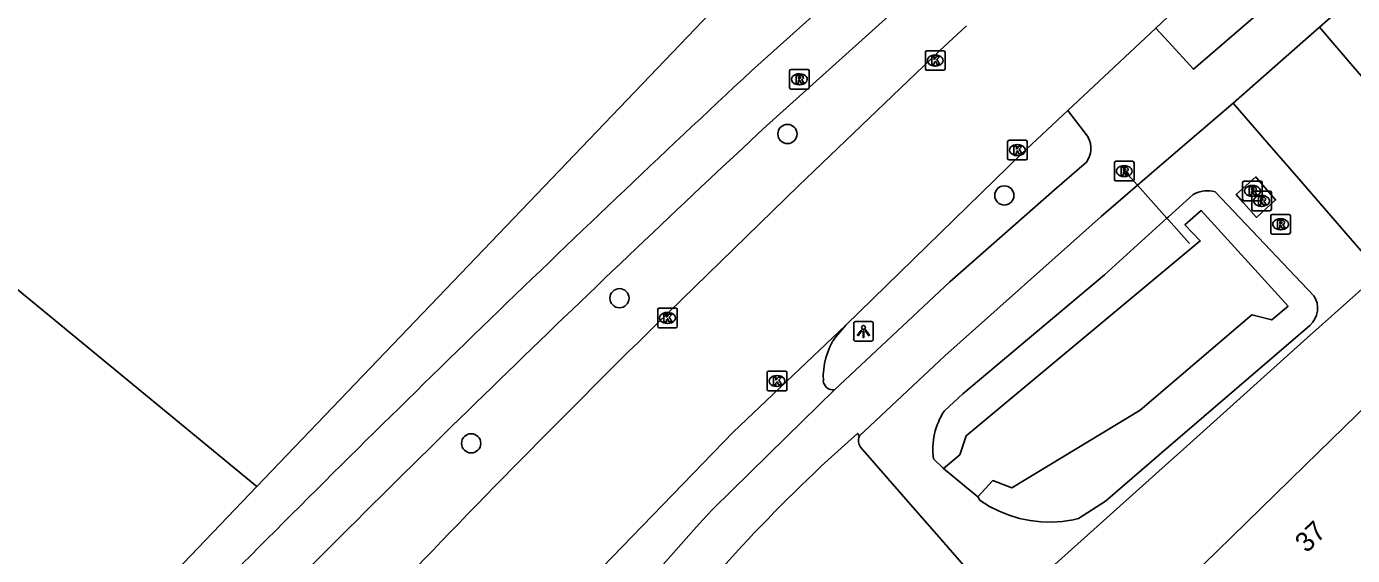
# Model space of a CAD drawing. Extents: x 156141 to 158132, y 385651 to 388399.
# Drawn here: x 156441.8 to 156509.4, y 386826.5 to 386853.4 of the extents above; entities that cross this region are included whole.
import ezdxf

# ---------------------------------------------------------------- set-up
doc = ezdxf.new("R2010")
doc.units = 0
for name, color, linetype in [('IMGEO_Boom', 7, 'Continuous'), ('IMGEO_Damwand', 7, 'Continuous'), ('IMGEO_Duiker', 7, 'Continuous'), ('IMGEO_Fietspad_gesloten', 7, 'Continuous'), ('IMGEO_Groenvoorziening', 7, 'Continuous'), ('IMGEO_Kolk', 7, 'Continuous'), ('IMGEO_Lichtpunt', 7, 'Continuous'), ('IMGEO_Loofbos', 7, 'Continuous'), ('IMGEO_Muur', 7, 'Continuous'), ('IMGEO_Pand', 7, 'Continuous'), ('IMGEO_Pand_nummerreeks', 7, 'Continuous'), ('IMGEO_Rijbaan_lokaal_gesloten', 7, 'Continuous'), ('IMGEO_Rijbaan_lokaal_open', 7, 'Continuous'), ('IMGEO_Rioolput', 7, 'Continuous'), ('IMGEO_Waterloop', 7, 'Continuous')]:
    doc.layers.add(name, color=color, linetype=linetype)

msp = doc.modelspace()

# ---------------------------------------------------------------- linework, layer by layer
at = {"layer": 'IMGEO_Boom'}
for centre in [(156480.568, 386847.96), (156491.626, 386844.826), (156472.004, 386839.585), (156464.441, 386832.183)]:
    msp.add_circle(centre, 0.489, dxfattribs=at)
at = {"layer": 'IMGEO_Damwand'}
msp.add_lwpolyline([(156506.093, 386839.179), (156501.667, 386844.053), (156500.837, 386843.324)], dxfattribs=at)
at = {"layer": 'IMGEO_Duiker'}
msp.add_lwpolyline([(156501.074, 386842.375), (156500, 386843.576), (156499.919, 386843.667), (156498.417, 386845.347), (156497.76, 386846.082)], dxfattribs=at)
at = {"layer": 'IMGEO_Fietspad_gesloten'}
for points in [[(156507.703, 386853.398), (156512.09, 386857.271), (156538.111, 386880.059)], [(156486.891, 386858.499), (156478.74, 386851.184)], [(156479.499, 386848.37), (156488.601, 386856.57)], [(156503.3, 386849.53), (156507.703, 386853.398)], [(156484.24, 386832.56), (156488.601, 386836.651), (156496.558, 386843.756), (156498.417, 386845.347), (156500, 386846.703), (156503.3, 386849.53)], [(156494.861, 386849.158), (156495.912, 386847.781)], [(156495.815, 386846.527), (156494.181, 386845.112), (156488.853, 386840.427), (156482.97, 386834.92)]]:
    msp.add_lwpolyline(points, dxfattribs=at)
for centre, radius, start, end in [((157123.713, 386159.175), 945.974, 132.985141, 135.281185), ((157069.291, 386214.847), 865.567, 132.95264, 135.361886), ((156494.838, 386847.233), 1.205, 324.12857, 27.02511)]:
    msp.add_arc(centre, radius, start, end, dxfattribs=at)
at = {"layer": 'IMGEO_Groenvoorziening'}
for points in [[(156541.121, 386876.586), (156521.047, 386859.086), (156514.467, 386853.349), (156510.617, 386850.009), (156509.404, 386851.42), (156507.703, 386853.398)], [(156503.3, 386849.53), (156505.031, 386847.528), (156506.198, 386846.177), (156510.785, 386840.87), (156507.066, 386837.556), (156500.596, 386831.732), (156500, 386831.198), (156491.571, 386823.646)], [(156503.825, 386844.452), (156503.449, 386844.872), (156504.446, 386845.766), (156504.581, 386845.61), (156505.46, 386844.595), (156504.495, 386843.703), (156503.825, 386844.452)], [(156501.249, 386844.873), (156500, 386843.741), (156499.919, 386843.667), (156496.734, 386840.782), (156489.517, 386834.707), (156488.569, 386833.834)], [(156507.413, 386839.712), (156502.375, 386845.014), (156502.239, 386845.043)], [(156490.282, 386829.462), (156490.398, 386829.263), (156490.866, 386828.97), (156491.358, 386828.719), (156491.87, 386828.514), (156492.398, 386828.355), (156492.939, 386828.244), (156493.487, 386828.181), (156494.039, 386828.168), (156494.59, 386828.205), (156495.135, 386828.29), (156495.411, 386828.352), (156496.782, 386829.23), (156500, 386831.998), (156507.213, 386838.2)], [(156488.019, 386831.388), (156488.526, 386830.905)]]:
    msp.add_lwpolyline(points, dxfattribs=at)
for centre, radius, start, end in [((156501.987, 386843.543), 1.521, 80.45967, 119.02761), ((156506.418, 386839.074), 1.182, 312.27222, 32.65765), ((156491.507, 386831.888), 3.524, 146.4902, 188.16464)]:
    msp.add_arc(centre, radius, start, end, dxfattribs=at)
at = {"layer": 'IMGEO_Kolk'}
for p, q in [((156487.602, 386851.28), (156487.602, 386852.132)), ((156487.677, 386852.206), (156488.529, 386852.206)), ((156488.09, 386851.986), (156488.115, 386851.986)), ((156488.603, 386852.132), (156488.603, 386851.28)), ((156488.529, 386851.206), (156487.677, 386851.206)), ((156488.113, 386851.426), (156488.088, 386851.426)), ((156491.797, 386846.712), (156491.797, 386847.564)), ((156491.872, 386847.638), (156492.724, 386847.638)), ((156492.285, 386847.418), (156492.31, 386847.418)), ((156492.798, 386847.564), (156492.798, 386846.712)), ((156492.724, 386846.638), (156491.872, 386846.638)), ((156492.308, 386846.858), (156492.283, 386846.858)), ((156474.026, 386839.077), (156474.878, 386839.077)), ((156473.951, 386838.151), (156473.951, 386839.003)), ((156474.439, 386838.857), (156474.464, 386838.857)), ((156474.952, 386839.003), (156474.952, 386838.151)), ((156474.878, 386838.077), (156474.026, 386838.077)), ((156474.462, 386838.297), (156474.437, 386838.297)), ((156479.534, 386834.937), (156479.534, 386835.789)), ((156479.609, 386835.863), (156480.461, 386835.863)), ((156480.022, 386835.643), (156480.047, 386835.643)), ((156480.535, 386835.789), (156480.535, 386834.937)), ((156480.045, 386835.083), (156480.02, 386835.083)), ((156480.461, 386834.863), (156479.609, 386834.863))]:
    msp.add_line(p, q, dxfattribs=at)
for points in [[(156487.602, 386851.28), (156487.602, 386852.132)], [(156487.677, 386852.206), (156488.529, 386852.206)], [(156487.923, 386851.906), (156488.046, 386851.906), (156488.046, 386851.755), (156488.176, 386851.906), (156488.34, 386851.906), (156488.194, 386851.755), (156488.347, 386851.506), (156488.195, 386851.506), (156488.11, 386851.67), (156488.046, 386851.603), (156488.046, 386851.506), (156487.923, 386851.506), (156487.923, 386851.906)], [(156488.603, 386852.132), (156488.603, 386851.28)], [(156488.529, 386851.206), (156487.677, 386851.206)], [(156491.797, 386846.712), (156491.797, 386847.564)], [(156491.872, 386847.638), (156492.724, 386847.638)], [(156492.118, 386847.338), (156492.241, 386847.338), (156492.241, 386847.187), (156492.371, 386847.338), (156492.535, 386847.338), (156492.389, 386847.187), (156492.542, 386846.938), (156492.39, 386846.938), (156492.305, 386847.102), (156492.241, 386847.035), (156492.241, 386846.938), (156492.118, 386846.938), (156492.118, 386847.338)], [(156492.798, 386847.564), (156492.798, 386846.712)], [(156492.724, 386846.638), (156491.872, 386846.638)], [(156474.026, 386839.077), (156474.878, 386839.077)], [(156473.951, 386838.151), (156473.951, 386839.003)], [(156474.272, 386838.777), (156474.395, 386838.777), (156474.395, 386838.626), (156474.525, 386838.777), (156474.689, 386838.777), (156474.543, 386838.626), (156474.696, 386838.377), (156474.544, 386838.377), (156474.459, 386838.541), (156474.395, 386838.474), (156474.395, 386838.377), (156474.272, 386838.377), (156474.272, 386838.777)], [(156474.952, 386839.003), (156474.952, 386838.151)], [(156474.878, 386838.077), (156474.026, 386838.077)], [(156479.534, 386834.937), (156479.534, 386835.789)], [(156479.609, 386835.863), (156480.461, 386835.863)], [(156480.535, 386835.789), (156480.535, 386834.937)], [(156479.855, 386835.563), (156479.978, 386835.563), (156479.978, 386835.412), (156480.108, 386835.563), (156480.272, 386835.563), (156480.126, 386835.412), (156480.279, 386835.163), (156480.127, 386835.163), (156480.042, 386835.327), (156479.978, 386835.26), (156479.978, 386835.163), (156479.855, 386835.163), (156479.855, 386835.563)], [(156480.461, 386834.863), (156479.609, 386834.863)]]:
    msp.add_lwpolyline(points, dxfattribs=at)
for centre, start, end in [((156487.679, 386852.13), 91.55205, 178.44795), ((156487.679, 386852.13), 91.55205, 178.44795), ((156488.527, 386852.13), 1.55205, 88.44795), ((156488.527, 386852.13), 1.55205, 88.44795), ((156487.679, 386851.282), 181.55205, 268.44795), ((156487.679, 386851.282), 181.55205, 268.44795), ((156488.527, 386851.282), 271.55205, 358.44795), ((156488.527, 386851.282), 271.55205, 358.44795), ((156491.874, 386847.562), 91.55205, 178.44795), ((156491.874, 386847.562), 91.55205, 178.44795), ((156492.722, 386847.562), 1.55205, 88.44795), ((156492.722, 386847.562), 1.55205, 88.44795), ((156491.874, 386846.714), 181.55205, 268.44795), ((156491.874, 386846.714), 181.55205, 268.44795), ((156492.722, 386846.714), 271.55205, 358.44795), ((156492.722, 386846.714), 271.55205, 358.44795), ((156474.028, 386839.001), 91.55205, 178.44795), ((156474.028, 386839.001), 91.55205, 178.44795), ((156474.876, 386839.001), 1.55205, 88.44795), ((156474.876, 386839.001), 1.55205, 88.44795), ((156474.028, 386838.153), 181.55205, 268.44795), ((156474.028, 386838.153), 181.55205, 268.44795), ((156474.876, 386838.153), 271.55205, 358.44795), ((156474.876, 386838.153), 271.55205, 358.44795), ((156479.611, 386835.787), 91.55205, 178.44795), ((156479.611, 386835.787), 91.55205, 178.44795), ((156480.459, 386835.787), 1.55205, 88.44795), ((156480.459, 386835.787), 1.55205, 88.44795), ((156479.611, 386834.939), 181.55205, 268.44795), ((156479.611, 386834.939), 181.55205, 268.44795), ((156480.459, 386834.939), 271.55205, 358.44795), ((156480.459, 386834.939), 271.55205, 358.44795)]:
    msp.add_arc(centre, 0.0765, start, end, dxfattribs=at)
for centre, major_axis, ratio, start_param, end_param in [((156488.089, 386851.706), (-0.387, 0.002), 0.722429, 4.712389, 7.853982), ((156488.114, 386851.706), (-0.39, 0.002), 0.717154, 1.570796, 4.712389), ((156492.284, 386847.138), (-0.387, 0.002), 0.722429, 4.712389, 7.853982), ((156492.309, 386847.138), (-0.39, 0.002), 0.717154, 1.570796, 4.712389), ((156474.438, 386838.577), (-0.387, 0.002), 0.722429, 4.712389, 7.853982), ((156474.463, 386838.577), (-0.39, 0.002), 0.717154, 1.570796, 4.712389), ((156480.021, 386835.363), (-0.387, 0.002), 0.722429, 4.712389, 7.853982), ((156480.046, 386835.363), (-0.39, 0.002), 0.717154, 1.570796, 4.712389)]:
    msp.add_ellipse(centre, major_axis=major_axis, ratio=ratio, start_param=start_param, end_param=end_param, dxfattribs=at)
at = {"layer": 'IMGEO_Lichtpunt'}
for p, q in [((156484.848, 386838.39), (156484.04, 386838.39)), ((156484.848, 386838.39), (156484.04, 386838.39)), ((156483.946, 386838.295), (156483.946, 386837.488)), ((156483.946, 386838.295), (156483.946, 386837.488)), ((156484.942, 386837.488), (156484.942, 386838.295)), ((156484.942, 386837.488), (156484.942, 386838.295)), ((156484.04, 386837.394), (156484.848, 386837.394)), ((156484.04, 386837.394), (156484.848, 386837.394))]:
    msp.add_line(p, q, dxfattribs=at)
for points in [[(156484.32, 386837.959), (156484.359, 386837.931), (156484.171, 386837.669), (156484.133, 386837.696), (156484.32, 386837.959)], [(156484.422, 386837.911), (156484.469, 386837.911), (156484.469, 386837.589), (156484.422, 386837.589), (156484.422, 386837.911)], [(156484.532, 386837.931), (156484.57, 386837.958), (156484.757, 386837.696), (156484.718, 386837.668), (156484.532, 386837.931)]]:
    msp.add_lwpolyline(points, dxfattribs=at)
msp.add_circle((156484.445, 386838.093), 0.0994, dxfattribs=at)
for centre, start, end in [((156484.04, 386838.295), 90, 180), ((156484.04, 386838.295), 90, 180), ((156484.848, 386838.295), 0, 90), ((156484.848, 386838.295), 0, 90), ((156484.04, 386837.488), 180, 270), ((156484.04, 386837.488), 180, 270), ((156484.848, 386837.488), 270, 0), ((156484.848, 386837.488), 270, 360)]:
    msp.add_arc(centre, 0.0946, start, end, dxfattribs=at)
at = {"layer": 'IMGEO_Loofbos'}
for points in [[(156477.017, 386854.528), (156453.514, 386829.977)], [(156453.514, 386829.977), (156432.819, 386847.005)], [(156319.44, 386711.006), (156328.204, 386706.015), (156336.412, 386700.768), (156340.458, 386698.073), (156352.908, 386693.536), (156356.441, 386698.274), (156368.107, 386728.082), (156373.627, 386738.284), (156377.846, 386743.729), (156378.025, 386743.673), (156392.935, 386762.089), (156409.337, 386781.78), (156423.12, 386797.547), (156438.936, 386814.747), (156453.514, 386829.977)]]:
    msp.add_lwpolyline(points, dxfattribs=at)
at = {"layer": 'IMGEO_Muur'}
msp.add_lwpolyline([(156491.044, 386830.284), (156490.282, 386829.462), (156488.526, 386830.905), (156489.363, 386831.601)], dxfattribs=at)
at = {"layer": 'IMGEO_Pand'}
msp.add_lwpolyline([(156573.959, 386778.499), (156540.633, 386750), (156539.875, 386749.352), (156539.321, 386750), (156500.018, 386795.984), (156500.686, 386796.557), (156500.873, 386796.717), (156507.654, 386802.533), (156507.837, 386802.69), (156508.595, 386803.34), (156500, 386813.377), (156498.7, 386814.895), (156500, 386815.987), (156501.008, 386816.835), (156500, 386818.009), (156497.073, 386821.418), (156500, 386824.274), (156502.476, 386826.686), (156506.952, 386831.048), (156513.62, 386837.545), (156518.505, 386831.859), (156524.165, 386836.688), (156573.959, 386778.499)], dxfattribs=at)
at = {"layer": 'IMGEO_Rijbaan_lokaal_gesloten'}
for points in [[(156499.353, 386853.356), (156499.631, 386853.615), (156500, 386853.959), (156504.215, 386857.841), (156504.917, 386858.465)], [(156489.706, 386853.481), (156488.33, 386852.194), (156481.132, 386845.308), (156473.853, 386838.223)], [(156494.861, 386849.158), (156499.353, 386853.356)], [(156483.548, 386838.213), (156492.502, 386846.939), (156494.861, 386849.158)], [(156470.076, 386824.776), (156477.801, 386832.749), (156483.548, 386838.213)]]:
    msp.add_lwpolyline(points, dxfattribs=at)
msp.add_arc((156881.446, 386423.628), 581.395, 134.512068, 136.552486, dxfattribs=at)
at = {"layer": 'IMGEO_Rijbaan_lokaal_open'}
for points in [[(156506.139, 386855.462), (156501.282, 386851.264), (156500, 386852.654), (156499.353, 386853.356)], [(156483.028, 386837.623), (156483.548, 386838.213)], [(156482.97, 386834.92), (156480.507, 386832.5), (156476.793, 386828.86), (156476.444, 386828.486), (156475.932, 386827.932), (156473.453, 386825.124)], [(156482.647, 386831.339), (156484.137, 386832.688), (156484.24, 386832.56)], [(156484.3, 386831.993), (156487.086, 386828.795), (156488.423, 386827.259), (156491.571, 386823.646)]]:
    msp.add_lwpolyline(points, dxfattribs=at)
for centre, radius, start, end in [((156486.043, 386835.567), 3.649, 145.71498, 183.02132), ((156482.884, 386835.398), 0.486, 182.76554, 280.13545), ((156484.719, 386832.324), 0.534, 153.78333, 218.2978), ((156539.223, 386770.338), 83.198, 132.84474, 138.12742)]:
    msp.add_arc(centre, radius, start, end, dxfattribs=at)
at = {"layer": 'IMGEO_Rioolput'}
for p, q in [((156480.752, 386851.248), (156481.604, 386851.248)), ((156480.677, 386850.322), (156480.677, 386851.174)), ((156481.165, 386851.028), (156481.19, 386851.028)), ((156481.678, 386851.174), (156481.678, 386850.322)), ((156481.604, 386850.248), (156480.752, 386850.248)), ((156481.188, 386850.468), (156481.163, 386850.468)), ((156497.243, 386845.639), (156497.243, 386846.491)), ((156497.318, 386846.565), (156498.17, 386846.565)), ((156498.244, 386846.491), (156498.244, 386845.639)), ((156497.754, 386845.785), (156497.729, 386845.785)), ((156497.731, 386846.345), (156497.756, 386846.345)), ((156498.17, 386845.565), (156497.318, 386845.565)), ((156503.778, 386844.63), (156503.778, 386845.482)), ((156503.853, 386845.556), (156504.705, 386845.556)), ((156504.266, 386845.336), (156504.291, 386845.336)), ((156504.779, 386845.482), (156504.779, 386844.63)), ((156504.705, 386844.556), (156503.853, 386844.556)), ((156504.245, 386844.121), (156504.245, 386844.973)), ((156504.289, 386844.776), (156504.264, 386844.776)), ((156504.32, 386845.047), (156505.172, 386845.047)), ((156504.733, 386844.827), (156504.758, 386844.827)), ((156505.246, 386844.973), (156505.246, 386844.121)), ((156505.172, 386844.047), (156504.32, 386844.047)), ((156504.756, 386844.267), (156504.731, 386844.267)), ((156505.213, 386842.93), (156505.213, 386843.782)), ((156505.288, 386843.856), (156506.14, 386843.856)), ((156506.214, 386843.782), (156506.214, 386842.93)), ((156505.724, 386843.076), (156505.699, 386843.076)), ((156505.701, 386843.636), (156505.726, 386843.636)), ((156506.14, 386842.856), (156505.288, 386842.856))]:
    msp.add_line(p, q, dxfattribs=at)
for points in [[(156480.752, 386851.248), (156481.604, 386851.248)], [(156480.677, 386850.322), (156480.677, 386851.174)], [(156481.266, 386850.946), (156481.014, 386850.948), (156481.014, 386850.548)], [(156481.014, 386850.548), (156481.138, 386850.548), (156481.138, 386850.71), (156481.149, 386850.71)], [(156481.192, 386850.867), (156481.138, 386850.867), (156481.138, 386850.786)], [(156481.138, 386850.786), (156481.19, 386850.786)], [(156481.196, 386850.681), (156481.267, 386850.548), (156481.407, 386850.548), (156481.342, 386850.674)], [(156481.678, 386851.174), (156481.678, 386850.322)], [(156481.604, 386850.248), (156480.752, 386850.248)], [(156497.243, 386845.639), (156497.243, 386846.491)], [(156497.318, 386846.565), (156498.17, 386846.565)], [(156498.244, 386846.491), (156498.244, 386845.639)], [(156497.832, 386846.263), (156497.58, 386846.265), (156497.58, 386845.865)], [(156497.58, 386845.865), (156497.704, 386845.865), (156497.704, 386846.027), (156497.715, 386846.027)], [(156497.758, 386846.184), (156497.704, 386846.184), (156497.704, 386846.103)], [(156497.704, 386846.103), (156497.756, 386846.103)], [(156497.762, 386845.998), (156497.833, 386845.865), (156497.973, 386845.865), (156497.908, 386845.991)], [(156498.17, 386845.565), (156497.318, 386845.565)], [(156503.778, 386844.63), (156503.778, 386845.482)], [(156503.853, 386845.556), (156504.705, 386845.556)], [(156504.367, 386845.254), (156504.115, 386845.256), (156504.115, 386844.856)], [(156504.293, 386845.175), (156504.239, 386845.175), (156504.239, 386845.094)], [(156504.779, 386845.482), (156504.779, 386844.63)], [(156504.705, 386844.556), (156503.853, 386844.556)], [(156504.115, 386844.856), (156504.239, 386844.856), (156504.239, 386845.018), (156504.25, 386845.018)], [(156504.239, 386845.094), (156504.291, 386845.094)], [(156504.245, 386844.121), (156504.245, 386844.973)], [(156504.297, 386844.989), (156504.368, 386844.856), (156504.508, 386844.856), (156504.443, 386844.982)], [(156504.32, 386845.047), (156505.172, 386845.047)], [(156504.834, 386844.745), (156504.582, 386844.747), (156504.582, 386844.347)], [(156504.582, 386844.347), (156504.706, 386844.347), (156504.706, 386844.509), (156504.717, 386844.509)], [(156504.76, 386844.666), (156504.706, 386844.666), (156504.706, 386844.585)], [(156504.706, 386844.585), (156504.758, 386844.585)], [(156504.764, 386844.48), (156504.835, 386844.347), (156504.975, 386844.347), (156504.91, 386844.473)], [(156505.246, 386844.973), (156505.246, 386844.121)], [(156505.172, 386844.047), (156504.32, 386844.047)], [(156505.213, 386842.93), (156505.213, 386843.782)], [(156505.288, 386843.856), (156506.14, 386843.856)], [(156506.214, 386843.782), (156506.214, 386842.93)], [(156505.802, 386843.554), (156505.55, 386843.556), (156505.55, 386843.156)], [(156505.55, 386843.156), (156505.674, 386843.156), (156505.674, 386843.318), (156505.685, 386843.318)], [(156505.728, 386843.475), (156505.674, 386843.475), (156505.674, 386843.394)], [(156505.674, 386843.394), (156505.726, 386843.394)], [(156505.732, 386843.289), (156505.803, 386843.156), (156505.943, 386843.156), (156505.878, 386843.282)], [(156506.14, 386842.856), (156505.288, 386842.856)]]:
    msp.add_lwpolyline(points, dxfattribs=at)
for centre, radius, start, end in [((156480.754, 386851.172), 0.0765, 91.55205, 178.44795), ((156480.754, 386851.172), 0.0765, 91.55205, 178.44795), ((156481.602, 386851.172), 0.0765, 1.55205, 88.44795), ((156481.602, 386851.172), 0.0765, 1.55205, 88.44795), ((156481.148, 386850.657), 0.0533, 26.02933, 88.69889), ((156481.174, 386850.975), 0.19, 274.7715, 282.96867), ((156481.198, 386850.771), 0.0964, 77.00612, 93.18647), ((156481.212, 386850.828), 0.0378, 276.66336, 79.67722), ((156481.265, 386850.836), 0.109, 350.36119, 89.41601), ((156481.263, 386850.836), 0.112, 277.58423, 350.98172), ((156481.247, 386850.621), 0.108, 29.51342, 73.79051), ((156480.754, 386850.324), 0.0765, 181.55205, 268.44795), ((156480.754, 386850.324), 0.0765, 181.55205, 268.44795), ((156481.602, 386850.324), 0.0765, 271.55205, 358.44795), ((156481.602, 386850.324), 0.0765, 271.55205, 358.44795), ((156497.32, 386846.489), 0.0765, 91.55205, 178.44795), ((156497.32, 386846.489), 0.0765, 91.55205, 178.44795), ((156498.168, 386846.489), 0.0765, 1.55205, 88.44795), ((156498.168, 386846.489), 0.0765, 1.55205, 88.44795), ((156497.714, 386845.974), 0.0533, 26.02933, 88.69889), ((156497.74, 386846.292), 0.19, 274.7715, 282.96867), ((156497.764, 386846.088), 0.0964, 77.00612, 93.18647), ((156497.778, 386846.145), 0.0378, 276.66336, 79.67722), ((156497.831, 386846.153), 0.109, 350.36119, 89.41601), ((156497.829, 386846.153), 0.112, 277.58423, 350.98172), ((156497.813, 386845.938), 0.108, 29.51342, 73.79051), ((156497.32, 386845.641), 0.0765, 181.55205, 268.44795), ((156497.32, 386845.641), 0.0765, 181.55205, 268.44795), ((156498.168, 386845.641), 0.0765, 271.55205, 358.44795), ((156498.168, 386845.641), 0.0765, 271.55205, 358.44795), ((156503.855, 386845.48), 0.0765, 91.55205, 178.44795), ((156503.855, 386845.48), 0.0765, 91.55205, 178.44795), ((156504.299, 386845.079), 0.0964, 77.00612, 93.18647), ((156504.313, 386845.136), 0.0378, 276.66336, 79.67722), ((156504.366, 386845.144), 0.109, 350.36119, 89.41601), ((156504.364, 386845.144), 0.112, 277.58423, 350.98172), ((156504.703, 386845.48), 0.0765, 1.55205, 88.44795), ((156504.703, 386845.48), 0.0765, 1.55205, 88.44795), ((156503.855, 386844.632), 0.0765, 181.55205, 268.44795), ((156503.855, 386844.632), 0.0765, 181.55205, 268.44795), ((156504.322, 386844.971), 0.0765, 91.55205, 178.44795), ((156504.322, 386844.971), 0.0765, 91.55205, 178.44795), ((156504.249, 386844.965), 0.0533, 26.02933, 88.69889), ((156504.275, 386845.283), 0.19, 274.7715, 282.96867), ((156504.348, 386844.929), 0.108, 29.51342, 73.79051), ((156504.703, 386844.632), 0.0765, 271.55205, 358.44795), ((156504.703, 386844.632), 0.0765, 271.55205, 358.44795), ((156504.716, 386844.456), 0.0533, 26.02933, 88.69889), ((156504.742, 386844.774), 0.19, 274.7715, 282.96867), ((156504.766, 386844.57), 0.0964, 77.00612, 93.18647), ((156504.78, 386844.627), 0.0378, 276.66336, 79.67722), ((156504.833, 386844.635), 0.109, 350.36119, 89.41601), ((156504.831, 386844.635), 0.112, 277.58423, 350.98172), ((156504.815, 386844.42), 0.108, 29.51342, 73.79051), ((156505.17, 386844.971), 0.0765, 1.55205, 88.44795), ((156505.17, 386844.971), 0.0765, 1.55205, 88.44795), ((156504.322, 386844.123), 0.0765, 181.55205, 268.44795), ((156504.322, 386844.123), 0.0765, 181.55205, 268.44795), ((156505.17, 386844.123), 0.0765, 271.55205, 358.44795), ((156505.17, 386844.123), 0.0765, 271.55205, 358.44795), ((156505.29, 386843.78), 0.0765, 91.55205, 178.44795), ((156505.29, 386843.78), 0.0765, 91.55205, 178.44795), ((156506.138, 386843.78), 0.0765, 1.55205, 88.44795), ((156506.138, 386843.78), 0.0765, 1.55205, 88.44795), ((156505.684, 386843.265), 0.0533, 26.02933, 88.69889), ((156505.71, 386843.583), 0.19, 274.7715, 282.96867), ((156505.734, 386843.379), 0.0964, 77.00612, 93.18647), ((156505.748, 386843.436), 0.0378, 276.66336, 79.67722), ((156505.801, 386843.444), 0.109, 350.36119, 89.41601), ((156505.799, 386843.444), 0.112, 277.58423, 350.98172), ((156505.783, 386843.229), 0.108, 29.51342, 73.79051), ((156505.29, 386842.932), 0.0765, 181.55205, 268.44795), ((156505.29, 386842.932), 0.0765, 181.55205, 268.44795), ((156506.138, 386842.932), 0.0765, 271.55205, 358.44795), ((156506.138, 386842.932), 0.0765, 271.55205, 358.44795)]:
    msp.add_arc(centre, radius, start, end, dxfattribs=at)
for centre, major_axis, ratio, start_param, end_param in [((156481.164, 386850.748), (-0.387, 0.002), 0.722429, 4.712389, 7.853982), ((156481.189, 386850.748), (-0.39, 0.002), 0.717154, 1.570796, 4.712389), ((156497.73, 386846.065), (-0.387, 0.002), 0.722429, 4.712389, 7.853982), ((156497.755, 386846.065), (-0.39, 0.002), 0.717154, 1.570796, 4.712389), ((156504.265, 386845.056), (-0.387, 0.002), 0.722429, 4.712389, 7.853982), ((156504.29, 386845.056), (-0.39, 0.002), 0.717154, 1.570796, 4.712389), ((156504.732, 386844.547), (-0.387, 0.002), 0.722429, 4.712389, 7.853982), ((156504.757, 386844.547), (-0.39, 0.002), 0.717154, 1.570796, 4.712389), ((156505.7, 386843.356), (-0.387, 0.002), 0.722429, 4.712389, 7.853982), ((156505.725, 386843.356), (-0.39, 0.002), 0.717154, 1.570796, 4.712389)]:
    msp.add_ellipse(centre, major_axis=major_axis, ratio=ratio, start_param=start_param, end_param=end_param, dxfattribs=at)
at = {"layer": 'IMGEO_Waterloop'}
for points in [[(156488.526, 386830.905), (156489.363, 386831.601), (156489.686, 386832.567), (156501.618, 386842.508), (156500.837, 386843.324), (156501.667, 386844.053), (156506.093, 386839.179), (156505.264, 386838.48), (156504.253, 386838.738), (156498.55, 386833.878), (156492.016, 386829.92), (156491.044, 386830.284), (156490.282, 386829.462)], [(156488.526, 386830.905), (156490.282, 386829.462)]]:
    msp.add_lwpolyline(points, dxfattribs=at)

# ---------------------------------------------------------------- texts
at = {"layer": 'IMGEO_Pand_nummerreeks'}
msp.add_text('37', height=1, rotation=44.26436, dxfattribs=at).set_placement((156507.045, 386826.556))

doc.saveas('drawing.dxf')
